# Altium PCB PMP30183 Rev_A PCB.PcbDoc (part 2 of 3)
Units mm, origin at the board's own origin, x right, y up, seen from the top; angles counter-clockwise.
Board outline 88.14 x 173.35 mm, 4 copper layers (Top Layer, Signal Layer 1, Signal Layer 2, Bottom Layer), stack 2.028 mm thick; 250 components, 133 nets, 589 pads, 226 vias.
Unrouted connection lines stored in the file: 1.
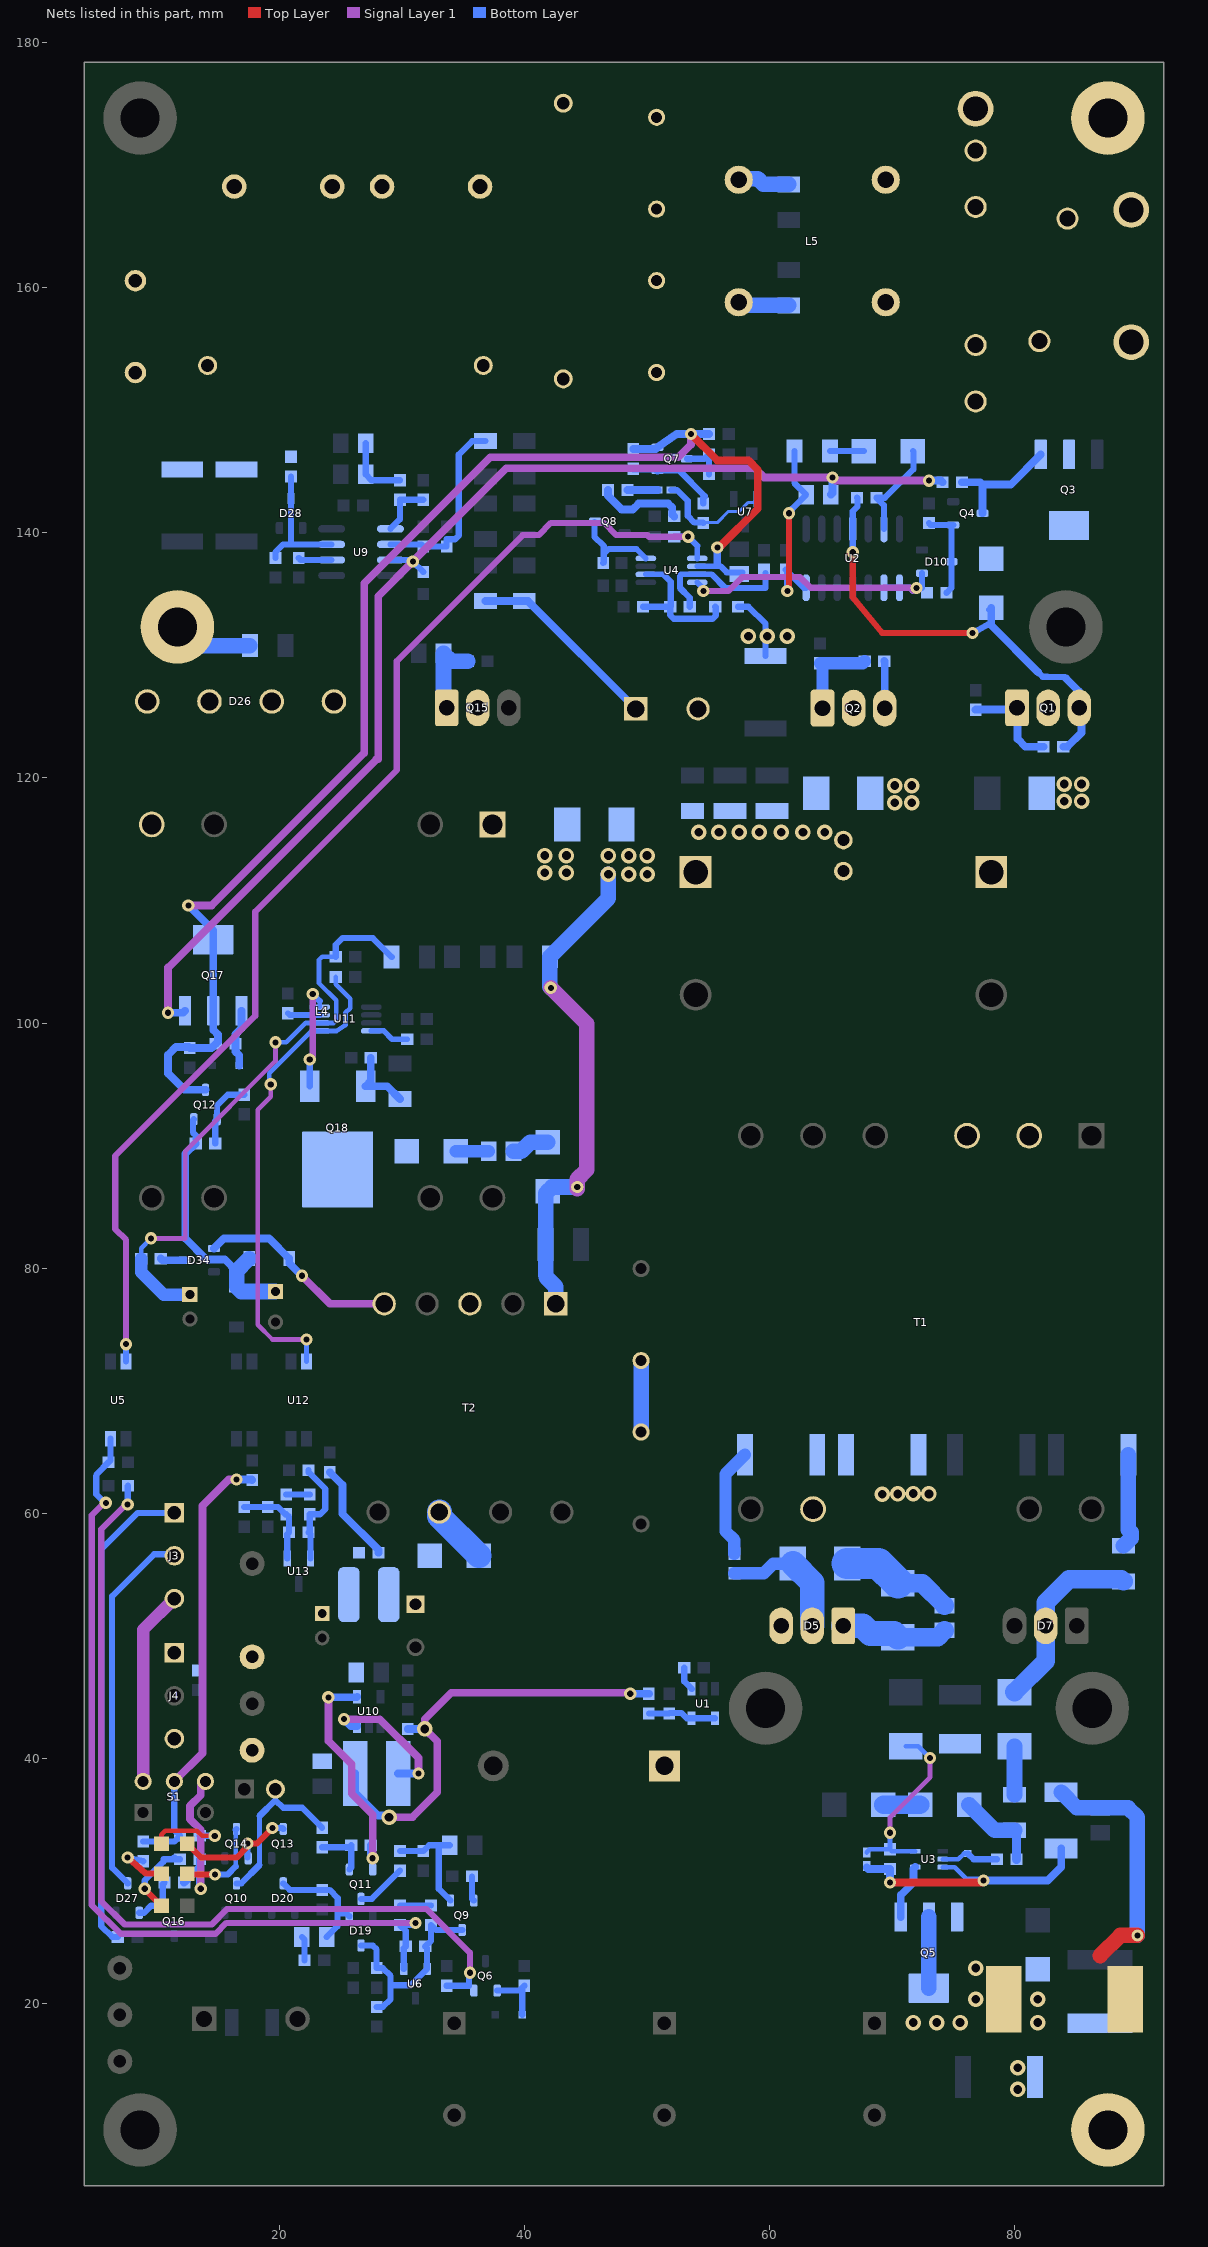
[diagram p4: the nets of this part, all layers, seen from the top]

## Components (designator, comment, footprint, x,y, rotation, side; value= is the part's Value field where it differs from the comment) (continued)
R86 "CRCW060310K0FKEA" 0603#1 19.05,59.69 r90 bottom
RT1 "B57237S0479M000" S237 8.255,156.845 r90 top
RV1 "B72220S0271K101" Epcos_B72220S0271K101 83.185,160.655 r270 top
S1 "200USP1T1A1M2RE" SW_200USP1T1A1M2 11.43,36.83 r90 top
T1 "750315800" Wurth_750315800 72.39,75.565 r270 top
T2 "7508110338" Wurth_7508110338 35.56,68.58 r270 top
TP1 "TESTPOINT" PAD_115mil-80milhole#1 89.535,166.37 r0 top
TP2 "TESTPOINT" PAD_115mil-80milhole#2 86.36,44.069 r0 top
TP3 "5000" Keystone5000 6.985,15.24 r180 top
TP4 "5001" Keystone5001 6.985,22.86 r180 top
TP5 "TESTPOINT" PAD_115mil-80milhole#2 87.63,173.863 r0 top locked
TP6 "TESTPOINT" PAD_115mil-80milhole#2 8.636,9.652 r0 top locked
TP7 "TESTPOINT" PAD_115mil-80milhole#2 8.636,173.863 r0 top locked
TP8 "TESTPOINT" PAD_115mil-80milhole#2 87.63,9.652 r0 top locked
TP9 "5003" Keystone5003 6.985,19.05 r180 top
TP10 "TESTPOINT" PAD_115mil-80milhole#2 59.69,44.069 r90 top
TP11 "TESTPOINT" PAD_115mil-80milhole#2 84.201,132.334 r0 top
TP12 "TESTPOINT" PAD_115mil-80milhole#2 11.684,132.334 r90 top
TP17 "TESTPOINT" PAD_115mil-80milhole#1 76.835,174.625 r90 top
TP19 "TESTPOINT" PAD_115mil-80milhole#1 89.535,155.575 r90 top
TP23 "5000" Keystone5000 17.78,48.26 r180 top
TP24 "5001" Keystone5001 17.78,44.45 r180 top
TP26 "5000" Keystone5000 17.78,40.64 r180 top
TP28 "5003" Keystone5003 17.78,55.88 r0 top
U1 "DS90LT012AHMF/NOPB" MF05A_N 54.61,44.45 r270 bottom
U2 "UCC27714DR" D0014A_N 66.81,137.929 r90 bottom
U3 "SN74LVC1G17DCKR" DCK0005A_N 73.025,31.75 r180 bottom
U4 "LM5021MMX-2" MUA08A_N 52.017,136.942 r180 bottom
U5 "TCMT1107" SOP-4 6.858,69.215 r90 bottom
U6 "TL431AIDBZR" DBZ0003A_N 31.115,21.59 r270 bottom
U7 "LMV431AIMF" MF03A_N 58.039,141.732 r270 bottom
U8 "TCMT1107" SOP-4 17.145,69.215 r90 bottom
U9 "UCC28180D" D0008A_N 26.67,138.43 r0 bottom
U10 "TPS560200DBVR" DBV0005A_N 27.305,43.815 r90 bottom
U11 "LM5021MMX-2" MUA08A_N 25.4,100.33 r0 bottom
U12 "TCMT1107" SOP-4 21.59,69.215 r90 bottom
U13 "LMV431BIMFX" MF03A_N 21.59,55.245 r270 bottom
XF1 "01000056Z" Littelfuse_0100-0020_54_56 76.835,168.91 r270 top
XF2 "01000056Z" Littelfuse_0100-0020_54_56 76.835,153.035 r270 top

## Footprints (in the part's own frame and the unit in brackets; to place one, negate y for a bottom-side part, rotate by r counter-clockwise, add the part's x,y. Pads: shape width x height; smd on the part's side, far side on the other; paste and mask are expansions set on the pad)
3M_923345-01-C [mil] "Wire Jumper"
  round 60 hole 38: 1(-50,0) 2(50,0)
  silkscreen extent -94,-44 94,44, body extent -63,-13 63,13, height 74
0603#1 [mm] "0603 from SM-752 data"
  rect 1x0.95 smd: 1(-0.8,0) 2(0.8,0)
  silkscreen extent -1.52,-0.69 1.52,0.69, body extent -0.87,-0.47 0.87,0.47, height 1
0603#2 [mm] "0603 from SM-752 data"
  rect 1x0.95 smd: 1(-0.927,0) 2(0.927,0)
  silkscreen extent -1.52,-0.69 1.52,0.69, body extent -0.87,-0.47 0.87,0.47, height 0.85
0603#3 [mm] "0603 from SM-752 data"
  rect 1x0.95 smd: 1(-0.927,0) 2(0.876,0)
  silkscreen extent -1.52,-0.69 1.52,0.69, body extent -0.87,-0.47 0.87,0.47, height 0.85
0805_HV [mil] "0805 with 30mil clearance between pads"
  rect 50x63 smd: 1(-40,0) 2(40,0)
  silkscreen extent -74,-40 74,40, body extent -43,-29 43,29, height 57
1206 [mm] "1206 from SM-752 data"
  rect 1.3x1.85 smd: 1(-1.45,0) 2(1.45,0)
  silkscreen extent -2.4,-1.21 2.4,1.21, body extent -1.7,-0.9 1.7,0.9, height 1.35
1210 [mm] "1210 from SM-752 data"
  rect 1.3x2.7 smd: 1(-1.45,0) 2(1.45,0)
  silkscreen extent -2.32,-1.57 2.32,1.57, body extent -1.7,-1.35 1.7,1.35, height 1.35
1210_280 [mm] "SMD, 2-Leads, Body 3.6x2.8mm, Height 2.8mm"
  rect 1.1x2.2 smd: 1(-1.65,0) 2(1.65,0)
  silkscreen extent -0.84,-1.4 0.84,1.4, body extent -1.8,-1.4 1.8,1.4, height 2.8
1812 [mm]
  rect 1.6x3.4 smd: 1(-2,0) 2(2,0)
  silkscreen extent -0.8,-1.6 0.8,1.6, body extent -2.4,-1.7 2.4,1.7, height 1.35
2010 [mm] "Chip Capacitor, Body 5.08x2.54mm, IPC Medium Density"
  rect 1.6x2.7 smd: 1(-2.3,0) 2(2.3,0)
  silkscreen extent -3.42,-1.65 3.42,1.65, body extent -2.73,-1.45 2.73,1.45, height 1.66
2220_200 [mm] "Chip Capacitor, Body 5.7x5.0mm, IPC Medium Density"
  rect 1.6x5.3 smd: 1(-2.6,0) 2(2.6,0)
  silkscreen extent -3.69,-2.94 3.69,2.94, body extent -2.95,-2.62 2.95,2.62, height 1.35
2512 [mm] "Chip Resistor, Body 6.3x3.2mm, IPC Medium Density"
  rect 1.3x3.4 smd: 1(-2.95,0) 2(2.95,0)
  silkscreen extent -1.9,-1.6 1.9,1.6, body extent -3.22,-1.67 3.22,1.67, height 0.71
750315814 [mm] "TH, 2-Leads, Dia 1160mil"
  rect 2.54x2.54 hole 1.5: 1(0,6.985)
  round 2.54 hole 1.5: 2(0,-6.985)
  silkscreen extent -14.73,-8.13 14.73,8.76, body extent -14.74,-8.13 14.74,8.13, height 31.48
750316373 [mm] "TH, 8-Leads, Body 35x35mm"
  rect 2.1x2.1 hole 1.6: 1(-15.24,13.905)
  round 2.1 hole 1.6: 2(-15.24,8.825) 5(-15.24,-8.825) 6(-15.24,-13.905) 7(15.24,-13.905) 8(15.24,-8.825) 11(15.24,8.825) 12(15.24,13.905)
  silkscreen extent -18.3,-17.5 17.5,17.5, body extent -17.5,-17.5 17.5,17.5, height 32
CAPPR3p5-8x16 [mm] "Kemet G8 package from ESY series 10/9/2012"
  rect 1.45x1.45 hole 0.95: 1(-1.75,0)
  round 1.45 hole 0.95: 2(1.75,0)
  silkscreen extent -5.91,-4.25 4.25,4.25, body extent -4.22,-4.24 4.24,4.24, height 18.01
CAPPR750W80D1600H3000 [mm] "Capacitor, Electrolytic, Radial; Body 16 x 30 mm (Dia.xH typ); Pin Spacing 7.5 mm (typ)"
  rect 1.85x1.85 hole 1.1: 1(-3.75,0)
  round 1.85 hole 1.1: 2(3.75,0)
  silkscreen extent -8.3,-8.3 8.3,8.3, body extent -8.19,-8.24 8.23,8.24, height 32.01
CAPRR2250W80L2550T850H1750 [mm] "PANASONIC"
  round 1.55 hole 1.05: 1(-11.25,0) 2(11.25,0)
  silkscreen extent -12.75,-4.25 12.75,4.25, body extent -12.75,-4.25 12.75,4.25, height 17.5
D0008A_N [mm] "SOIC, 8-Leads, Body 4.9x3.9mm, Pitch 1.27mm, IPC Medium Density"
  oval 2.2x0.6 smd: 1(-2.4,1.905) 2(-2.4,0.635) 3(-2.4,-0.635) 4(-2.4,-1.905) 5(2.4,-1.905) 6(2.4,-0.635) 7(2.4,0.635) 8(2.4,1.905)
  silkscreen extent -3.3,-2.5 0.9,2.5, body extent -3,-2.45 3,2.45, height 1.63
D0014A_N [mm] "SOIC, 14-Leads, Body 8.7x3.9mm, Pitch 1.27mm, IPC Medium Density"
  oval 2.2x0.6 smd: 1(-2.4,3.81) 2(-2.4,2.54) 3(-2.4,1.27) 4(-2.4,0) 5(-2.4,-1.27) 6(-2.4,-2.54) 7(-2.4,-3.81) 8(2.4,-3.81) 9(2.4,-2.54) 10(2.4,-1.27) 11(2.4,0) 12(2.4,1.27) 13(2.4,2.54) 14(2.4,3.81)
  silkscreen extent -3.3,-4.4 0.9,4.4, body extent -3.02,-4.32 3.02,4.32, height 1.59
DBV0005A_N [mm] "SOT23, 5-Leads, Body 2.9x1.6mm, Pitch 0.95mm, Lead Span 2.8mm, IPC Medium Density"
  rect 1.1x0.65 smd: 1(-1.2,0.95) 2(-1.2,0) 3(-1.2,-0.95) 4(1.2,-0.95) 5(1.2,0.95)
  silkscreen extent -0.25,-1.55 0.25,1.55, body extent -1.42,-1.46 1.42,1.46, height 1.08
DBZ0003A_N [mm] "SOT23, 3-Leads, Body 2.9x1.3mm, Pitch 0.95mm, Lead Span 2.4mm, IPC Medium Density"
  rrect17% 1x0.6 smd: 1(-1.2,0.95) 2(-1.2,-0.95) 3(1.2,0)
  silkscreen extent -1.65,-1.5 0.7,1.5, body extent -1.26,-1.46 1.26,1.46, height 0.98
DCK0005A_N [mm] "SOT353, 5-Leads, Body 2x1.3mm, Pitch 0.65mm, Lead Span 2.1mm, IPC Medium Density"
  rrect25% 0.85x0.4 smd: 1(-1.125,0.65) 2(-1.125,0) 3(-1.125,-0.65) 4(1.125,-0.65) 5(1.125,0.65)
  silkscreen extent -1.48,-1.02 0.55,1.1, body extent -1.14,-1 1.14,1, height 0.95
DPAK [mm] "D-PAK, 3-Pads, Body 6.22x6.73mm (max), TO-252AA using nominal STEP model"
  rrect6% 2.6x1.6 smd: 1(-3.4,2.28) 3(-3.4,-2.28)
  rrect2% 6.2x5.8 smd paste-2.9: 4(3.4,0)
  silkscreen extent -4.5,-3.3 4.7,3.28, body extent -3.86,-3.29 5.84,3.29, height 2.48
Epcos_B72220S0271K101 [mm] "TH, 2-Leads, Dia 21.5mm, Pin Spacing 10mm"
  round 1.8 hole 1.3: 1(-5,1.15) 2(5,-1.15)
  silkscreen extent -10.75,-2.7 10.75,2.7, body extent -10.66,-2.7 10.75,2.7, height 25.48
GBU [mm] "Comchip / Diodes Inc diode bridge"
  round 2 hole 1.5: 1(-7.62,0) 2(-2.54,0) 3(2.54,0) 4(7.62,0)
  silkscreen extent -11.15,-1.78 11.15,1.78, body extent -11.15,-1.76 11.15,1.8, height 21.55
IND_WE-CMB_L [mm] "Wurth"
  round 2.3 hole 1.321: 2(-5,6) 4(5,6) 7(5,-6) 9(-5,-6)
  silkscreen extent -13.75,-9.25 13.75,9.25, body extent -13.75,-9.25 13.75,9.25, height 33.02
Keystone5000 [mil] "For Keystone 500x miniature loop terminals"
  round 80 hole 40: 1(0,0)
  silkscreen extent -58,-58 58,58, body extent -49,-49 49,49, height 182
Keystone5001 [mil] "For Keystone 500x miniature loop terminals"
  round 80 hole 40: 1(0,0)
  silkscreen extent -58,-58 58,58, body extent -49,-49 49,49, height 182
Keystone5003 [mil] "For Keystone 500x miniature loop terminals"
  round 80 hole 40: 1(0,0)
  silkscreen extent -58,-58 58,58, body extent -49,-49 49,49, height 182
LED_LTST-C170 [mm] "LITE-ON"
  rect 1.2x1.2 smd: 1(-1.05,0) 2(1.05,0)
  silkscreen extent -1.6,-1 2.2,1, body extent -1.05,-0.67 1.05,0.67, height 1.1
Littelfuse_0100-0020_54_56 [mm] "Littelfuse"
  round 1.8 hole 1.3: 1(-2.3,0) 2(2.3,0)
  silkscreen extent -2.25,-2.97 2.25,2.97, body extent -2.55,-2.97 2.55,2.97, height 10.6
LTST-C170KGKT_Green [mm] "LITE-ON"
  rect 1.2x1.2 smd: 1(-1.05,0) 2(1.05,0)
  silkscreen extent -1.6,-1 2.2,1, body extent -1.05,-0.67 1.05,0.67, height 1.1
MF03A_N [mm] "SOT23, 3-Leads, Body 2.9x1.3mm, Pitch 0.95mm, Lead Span 2.4mm, IPC Medium Density"
  rect 1.3x0.6 smd: 1(-1.05,0.95) 2(-1.05,-0.95) 3(1.05,0)
  silkscreen extent -1.17,-1.5 0.7,1.92, body extent -0.7,-1.5 0.7,1.5, height 1.12
MF05A_N [mm] "SOT23, 5-Leads, Body 2.9x1.6mm, Pitch 0.95mm, Lead Span 2.8mm, IPC Medium Density"
  rect 1.1x0.65 smd: 1(-1.2,0.95) 2(-1.2,0) 3(-1.2,-0.95) 4(1.2,-0.95) 5(1.2,0.95)
  silkscreen extent -1.32,-1.55 0.25,1.95, body extent -0.9,-1.55 0.9,1.55, height 1.19
ML_500x500 [mm] "Rubycon"
  rect 1.2x1.2 hole 0.711: 1(-1,0)
  round 1.2 hole 0.711: 2(1,0)
  silkscreen extent -2.75,-2.75 2.75,2.75, body extent -2.73,-2.75 2.75,2.75, height 6.51
Molex_39357-0003 [mm] "Terminal Block, 3.5 mm, 3x1, TH"
  rect 1.6x1.6 hole 1.1: 1(-3.5,0)
  round 1.6 hole 1.1: 2(0,0) 3(3.5,0)
  silkscreen extent -5.61,-3.45 5.25,3.84, body extent -5.25,-3.45 5.16,3.84, height 8.51
Molex_0022284023 [mm] "Header, 2.54mm, 2x1, TH"
  rect 1.55x1.55 hole 1.02: 1(-1.27,0)
  round 1.55 hole 1.02: 2(1.27,0)
  silkscreen extent -2.54,-1.24 2.54,1.5, body extent -2.54,-1.24 2.54,1.24, height 8.4
MUA08A_N [mm] "TSOP, 8-Leads, Body 3x3mm, Pitch 0.65mm, IPC Medium Density"
  oval 1.7x0.45 smd: 1(-2.1,0.975) 2(-2.1,0.325) 3(-2.1,-0.325) 4(-2.1,-0.975) 5(2.1,-0.975) 6(2.1,-0.325) 7(2.1,0.325) 8(2.1,0.975)
  silkscreen extent -2.22,-1.55 0.85,1.87, body extent -1.6,-1.6 1.6,1.6, height 1.09
PAD_115mil-80milhole#1 [mil]
  round 115 hole 80: 1(0,0)
PAD_115mil-80milhole#2 [mil]
  round 236 hole 126: 1(0,0)
Phoenix_1732720 [mm] "Phoenix Contact"
  rect 2x2 hole 1.3 paste+0 mask+0.05: 1(-3.81,-1.1)
  round 2 hole 1.3 paste+0 mask+0.05: 2(3.81,-1.1)
  silkscreen extent -8.91,-6.4 7.62,6.4, body extent -8.19,-6.4 7.62,6.4, height 18.3
S237 [mm] "EPCOS"
  round 1.75 hole 1.1: 1(-3.75,0) 2(3.75,0)
  silkscreen extent -7.5,-3.5 7.5,3.5, body extent -7.47,-3.5 7.47,3.5, height 21.99
SMA [mm] "Molded Diode, 2-Leads, Body 4.3x2.6mm, IPC Medium Density, based on OnSemi component dimensions and land pattern"
  rect 2x2 smd: 1(-2,0) 2(2,0)
  silkscreen extent -3.66,-1.57 2.79,1.57, body extent -2.6,-1.3 2.6,1.3, height 2.42
SMB [mm] "Molded Diode, 2-Leads, Body 5.4x3.6mm, IPC Medium Density, based on OnSemi component dimensions"
  rect 2.159x2.743 smd: 1(-2.21,0) 2(2.21,0)
  silkscreen extent -3.94,-2.08 3.18,2.08, body extent -2.7,-1.8 2.7,1.8, height 2.32
SMQ_2200X2500 [mm] "United Chemi-Con Inc"
  rect 2.6x2.6 hole 2: 1(-5,0)
  round 2.6 hole 2: 2(5,0)
  silkscreen extent -11.6,-11.6 11.6,11.6, body extent -11.41,-11.48 11.47,11.48, height 27.01
SOD-123 [mm] "On Semi recommended land pattern"
  rect 0.915x1.22 smd: 1(-1.637,0) 2(1.637,0)
  silkscreen extent -2.74,-1.17 2.03,1.17, body extent -1.93,-0.9 1.93,0.9, height 1.35
sod-323 [mm] "NXP recommended land pattern"
  rect 0.6x0.6 smd paste-0.05: 1(-1.1,0) 2(1.1,0)
  silkscreen extent -2.06,-0.86 1.53,0.86, body extent -1.3,-0.67 1.3,0.68, height 1.1
SOD-523 [mm] "NXP Semiconductor recommended land pattern, nominal STEP model"
  rect 0.8x0.6 smd paste-0.05: 1(-0.55,0) 2(0.55,0)
  silkscreen extent -1.6,-0.63 1.2,0.64, body extent -0.8,-0.4 0.8,0.4, height 0.72
SOP-4 [mm] "Vishay Half Pitch Mini-Flat Package"
  rect 1.3x0.9 smd: 1(-3.15,0.635) 2(-3.15,-0.635) 3(3.15,-0.635) 4(3.15,0.635)
  silkscreen extent -2.2,-1.41 2.2,1.39, body extent -3.5,-1.4 3.5,1.4, height 2.12
SOT-23 [mm] "SOT23, 3-Leads, Body 2.9x1.3mm, Pitch 0.95mm, Lead Span 2.5mm, IPC Medium Density"
  rrect50% 1x0.6 smd: 1(-1.2,0.95) 2(-1.2,-0.95) 3(1.2,0)
  silkscreen extent -1.62,-1.5 0.7,1.5, body extent -1.16,-1.45 1.21,1.45, height 1
SOT-223 [mm] "SOT223/SC73, 4-Leads, Body 6.5x3.5mm, Pitch 2.3mm, Lead Span 7mm, IPC Medium Density"
  rrect10% 2.4x1 smd: 1(-2.9,2.3) 2(-2.9,0) 3(-2.9,-2.3)
  rrect4% 2.4x3.3 smd: 4(2.9,0)
  silkscreen extent -3.33,-3.35 1.4,3.35, body extent -3.5,-3.25 3.5,3.25, height 1.62
SW_200USP1T1A1M2 [mm] "TH, 5-Leads, Body 7x4.5mm, Pitch 2.54mm"
  rect 1.4x1.4 hole 0.9: 1(-1.27,2.54)
  round 1.4 hole 0.9: 3(-1.27,-2.54) 4(1.27,2.54) 5(1.27,0) 6(1.27,-2.54)
  silkscreen extent -2.7,-3.63 2.38,3.63, body extent -2.37,-3.62 2.38,3.63, height 11.13
TO-220-F2 [mm] "CREE"
  rect 1.9x1.9 hole 1.4: 1(-2.54,0)
  round 1.9 hole 1.4: 2(2.54,0)
  silkscreen extent -5.25,-1.64 5.26,3.01, body extent -5.25,-1.64 5.26,3.01, height 19.09
TO-220AB [mm] "Copied from Altium's version of TO3B"
  rrect25% 1.93x3 hole 1.27: 1(-2.54,0)
  oval 1.93x3 hole 1.27: 2(0,0) 3(2.54,0)
  silkscreen extent -5.61,-1.49 5.61,3.2, body extent -5.61,-1.49 5.61,3.2, height 19.42
VY2_1250x500x1650 [mm] "TH, 2- Leads, Body 12.5x5mm, Pin Spacing 7.5mm"
  round 1.4 hole 0.9: 1(-3.75,0) 2(3.75,0)
  silkscreen extent -6.25,-2.5 6.25,2.5, body extent -6.2,-2.5 6.25,2.5, height 16.49
WE-FI_1900x1050 [mm] "TH, 2-Leads, Dia 19mm, Pin Spacing 8mm"
  round 2 hole 1.25: 1(0,4) 2(0,-4)
  silkscreen extent -9.5,-5.25 9.5,5.25, body extent -9.5,-5.25 9.5,5.25, height 19
WE-PD2-S [mm] "WURTH"
  rrect50% 1.75x4.5 smd: 1(-1.625,0) 2(1.625,0)
  Top Layer region: 1.375,-2.25 0.75,-2.25 0.75,2.25 1.375,2.25
  Top Layer region: -1.375,2.25 -0.75,2.25 -0.75,-2.25 -1.375,-2.25
  silkscreen extent -0.4,-2.1 0.4,2.12, body extent -2.25,-2 2.25,2, height 3.18
WE-PD_1280 [mm] "Wurth Elektronik recommended land pattern"
  rect 2.9x5.4 smd: 1(-4.95,0) 2(4.95,0)
  silkscreen extent -6,-6 6,6, body extent -6,-6 6,6, height 8.01
WE-SPC_4838 [mm] "WURTH"
  rect 2x5.3 smd: 1(-1.75,0) 2(1.75,0)
  silkscreen extent -0.48,-2.65 0.48,2.65, body extent -2.55,-2.55 2.55,2.55, height 4.1
Wurth_750315800 [mm] "TH, 10-Leads, Body 37.34x35.56mm, Pitch 5.08mm"
  rect 2.1x2.1 hole 1.6: 1(-15.24,13.905)
  round 2.1 hole 1.6: 2(-15.24,8.825) 3(-15.24,3.745) 4(-15.24,-3.745) 5(-15.24,-8.825) 6(-15.24,-13.905) 7(15.24,-13.905) 8(15.24,-8.825) 11(15.24,8.825) 12(15.24,13.905)
  silkscreen extent -18.67,-17.78 18.67,17.78, body extent -18.67,-17.78 18.67,17.78, height 34.29
Wurth_7508110338 [mm] "TH, 9-Leads, Body 24.38x20.32mm"
  rect 1.9x1.9 hole 1.4: 1(-8.5,7)
  round 1.9 hole 1.4: 2(-8.5,3.5) 3(-8.5,0) 4(-8.5,-3.5) 5(-8.5,-7) 6(8.5,-7.5) 7(8.5,-2.5) 8(8.5,2.5) 9(8.5,7.5)
  silkscreen extent -12.19,-10.16 12.19,10.16, body extent -12.19,-10.16 12.19,10.16, height 16
ZL_630x1100 [mm] "RUBYCON"
  rect 1.25x1.25 hole 0.75: 1(-1.25,0)
  round 1.25 hole 0.75: 2(1.25,0)
  silkscreen extent -3.45,-3.45 3.45,3.45, body extent -3.37,-3.39 3.4,3.39, height 12.51
ZLJ_500x1100 [mm] "TH, 2-Leads, Dia 5mm,  Lead Spacing 2mm"
  rect 1.25x1.25 hole 0.75: 1(-1,0)
  round 1.25 hole 0.75: 2(1,0)
  silkscreen extent -2.75,-2.75 2.75,2.75, body extent -2.73,-2.75 2.75,2.75, height 12.51

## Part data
C1: "CAP, CERM, 0.01 µF, 630 V, +/- 10%, X7R, 1206"
C2 C3 C46: library part GRM32DR72J473KW01L, "CAP, CERM, 0.1 µF, 630 V, +/- 10%, X7T 1210"
C4: "CAP, CERM, 1000 pF, 630 V, +/- 5%, X7R, 0805"
C5 C8 C26 C45 C54: "CAP, CERM, 0.1uF, 50V, +/-10%, X7R, 0603"
C6: "CAP, CERM, 330 pF, 250 V, +/- 10%, X7R, 0603"
C7 C19 C20 C25 C32: "CAP, CERM, 1uF, 25V, +/-10%, X7R, 0603"
C9: "CAP, CERM, 220 pF, 630 V, +/- 5%, C0G/NP0, 1206"
C10 C11 C12: library part 400KXW100MEFC16X30, "CAP, AL, 1000 µF, 50 V, +/- 20%, TH"
C13: "CAP, CERM, 10 µF, 50 V, +/- 20%, X7R, 1210"
C14: "CAP, CERM, 1 µF, 250 V, +/- 10%, X7R, 2220"
C15 C16 C34 C60: "CAP, CERM, 4700 pF, 440 V, +/- 20%, Y5U, TH, 12.5x5mm"
C17: "CAP, CERM, 0.1 µF, 250 V, +/- 10%, X7R, 1812"
C18 C22 C24: "CAP, CERM, 100 pF, 50 V, +/- 5%, C0G/NP0, 0603"
C21 C28: "CAP, CERM, 1 µF, 50 V, +/- 10%, X7R, 0805"
C23 C55: "CAP, CERM, 0.33 µF, 16 V, +/- 10%, X7R, 0603"
C27 C39 C57: "CAP, CERM, 1000 pF, 50 V, +/- 10%, X7R, 0603"
C29: "CAP, CERM, 1000 pF, 50 V, +/- 10%, X8R, 0603"
C30: "CAP, CERM, 0.33 µF, 50 V, +/- 10%, X7R, 0805"
C31: "CAP, CERM, 4.7 µF, 25 V, +/- 10%, X7R, 0805"
C33: "CAP, CERM, 1000 pF, 630 V, +/- 10%, X7R, 1206"
C35 C36: library part ESMQ451VSN101MP25S, "CAP, AL, 150 µF, 450 V, +/- 20%, TH"
C37: "CAP, Film, 0.47 µF, 275 V, +/- 20%, TH"
C38: library part ECQ-U2A474ML, "CAP, Film, 1 µF, 275 V, +/- 20%, TH"
C40 C51: "CAP, CERM, 4.7 µF, 25 V, +/- 10%, X5R, 0805"
C41: "CAP, CERM, 2.2 µF, 16 V, +/- 10%, X7R, 0805"
C42: "CAP, CERM, 0.22 µF, 16 V, +/- 10%, X7R, 0603"
C43: "CAP, CERM, 820pF, 50V, +/-5%, C0G/NP0, 0603"
C44: "CAP, CERM, 2200 pF, 50 V, +/- 10%, X7R, 0603"
C47: library part ESY477M016AG8AA, "CAP, AL, 470uF, 16V, +/-20%, TH"
C48: library part 25ML22MEFC5X5, "CAP, AL, 100 µF, 16 V, +/- 20%, TH"
C49 C56: "CAP, CERM, 1uF, 16V, +/-10%, X7R, 0603"
C50: library part 35ZL56MEFCTA6.3X11, "CAP, AL, 47 µF, 35 V, +/- 20%, 0.25 ohm, TH"
C52: "CAP, CERM, 22 µF, 6.3 V, +/- 20%, X5R, 0805"
C53: library part 35ZLJ47MTA5X11, "CAP, AL, 10 µF, 50 V, +/- 20%, 1.4 ohm, TH"
C58: "CAP, CERM, 56pF, 50V, +/-5%, C0G/NP0, 0603"
C59: "CAP, CERM, 0.047 µF, 50 V, +/- 10%, X8R, 0603"
D1 D6: "Diode, Ultrafast, 600 V, 1 A, AEC-Q101, SMA"
D2 D11: "Diode, TVS, Uni, 150 V, 600 W, SMB"
D3 D9: "Diode, Schottky, 200 V, 3 A, SMB"
D4 D8: "Diode, Ultrafast, 600 V, 2 A, SMB"
D5 D7: library part VS-48CTQ060PBF, "Diode, Schottky, 200 V, 20 A, TH"
D10 D19 D20 D27 D28 D34: "Diode, Switching, 200 V, 0.2 A, SOT-23"
D12: "Diode, Zener, 5.1 V, 300 mW, SOD-523"
D13 D17: "Diode, TVS, Uni, 58 V, 400 W, SMA"
D14: "Diode, Schottky, 30 V, 0.2 A, SOD-323"
D15: "Diode, Ultrafast, 200 V, 1 A, SMA"
D16 D29: "Diode, Zener, 13 V, 200 mW, SOD-323"
D18: "Diode, Zener, 6.8 V, 300 mW, SOD-523"
D21: "LED, Yellow , SMD"
D22 D23: "LED, Green, SMD"
D24: library part MURS140-13-F, "Diode, Standard, 600 V, 3 A, SMB"
D25: library part C3D04060A, "Diode, X-Series PFC, 600 V, 6 A, TH"
D26: library part GBU8005, "Diode, Switching-Bridge, 600 V, 8 A, TH"
D30: library part STPS130A, "Diode, Schottky, 150 V, 1 A, SMA"
D31: "Diode, TVS, Uni, 120 V, 400 W, SMA"
D32: "Diode, Fast Rectifier, 800 V, 1 A, SMA"
D33: library part RF071M2S, "Diode, Ultrafast, 200 V, 1 A, SOD-123"
D35: library part MMSZ4711-V, "Diode, Zener, 27 V, 500 mW, SOD-123"
J1: "Jumper Wire, 100mil spacing, pkg of 200, TH"
J2: "Terminal Block, 2x1, 7.62mm, TH"
J3 J4: "Terminal Block, 3.5 mm, 3x1, Tin, TH"
J5: "Header, 2.54mm, 2x1, Tin, TH"
L1: library part 750315814, "Inductor, Toroid, 52 µH, 0.052 ohm, TH"
L2: "Inductor, Shielded Drum Core, Ferrite, 1 mH, 0.6 A, 1.82 ohm, SMD"
L3 L8: "Inductor, Toroid, Ferrite, 29 µH, 7.8 A, 0.015 ohm, TH"
L4: "Inductor, 500 µH, 0.03 ohm, TH"
L5: library part 744824310, "Coupled inductor, 3.3 mH, 4 A, 0.035 ohm, +/- 30%, TH"
L10: "Inductor, Shielded Drum Core, Ferrite, 4.7 µH, 1.82 A, 0.11 ohm, SMD"
L11: "Inductor, Shielded Drum Core, Ferrite, 22 µH, 1.1 A, 0.185 ohm, SMD"
Q1 Q2: "MOSFET, N-CH, 550 V, 17 A, TO-220AB"
Q3: library part FQT7N10LTF, "MOSFET, N-CH, 600 V, 300 mA, SOT-223"
Q4: "MOSFET, N-CH, 60 V, 0.24 A, SOT-23"
Q5: "MOSFET, P-CH, -240 V, -0.48 A, SOT-223"
Q6 Q8: library part "MMBT3904, Fairchild Semiconductor", "Transistor, NPN, 40 V, 0.2 A, SOT-23"
Q7 Q11: library part "MMBT3906, Fairchild Semiconductor", "Transistor, PNP, 40V, 0.2A, SOT-23"
Q9 Q10 Q13 Q14 Q16: "MOSFET, N-CH, 50 V, 0.22 A, SOT-23"
Q12: library part "MMBT2907A, Fairchild Semiconductor", "Transistor, PNP, 60 V, 0.8 A, SOT-23"
Q15: library part IPP50R199CP, "MOSFET, N-CH, 550 V, 23 A, TO-220AB"
Q17: library part "PZT2222A, Fairchild Semiconductor", "Transistor, NPN, 40 V, 0.5 A, SOT-223"
Q18: library part SPD04N80C3, "MOSFET, N-CH, 800 V, 2 A, DPAK"
R1: "RES, 2.21, 1%, 0.125 W, 0805"
R2: "RES, 2.20 ohm, 1%, 0.25W, 1206"
R3 R45 R46 R54: "RES, 100, 1%, 0.1 W, 0603"
R4: "RES, 29.4 k, 1%, 0.1 W, 0603"
R5 R6 R9 R12: "RES, 68.1, 1%, 1 W, 2512"
R7 R10: "RES, 4.75, 1%, 0.1 W, 0603"
R8 R13 R36 R41 R43 R51 R58 R67 R70 R86: "RES, 10.0k ohm, 1%, 0.1W, 0603"
R11 R17 R18 R19 R53: "RES, 1.00 k, 1%, 0.1 W, 0603"
R14: library part CSR2512FG68L0, "RES, 0.068, 1%, 2 W, 2512"
R15: "RES, 4.75 k, 1%, 0.1 W, 0603"
R16: "RES, 4.75 k, 1%, 0.25 W, 1206"
R20: "RES, 698k ohm, 1%, 0.25W, 1206"
R21: "RES, 23.7 k, 1%, 0.1 W, 0603"
R22: "RES, 3.32 k, 1%, 0.1 W, 0603"
R23 R84: "RES, 2.21k ohm, 1%, 0.1W, 0603"
R24: "RES, 68.1 k, 1%, 0.75 W, 2010"
R25 R29: "RES, 715k ohm, 1%, 0.25W, 1206"
R26: "RES, 16.5 k, 1%, 0.1 W, 0603"
R27 R33 R34: "RES, 68.1 k, 1%, 0.1 W, 0603"
R28: "RES, 33.2, 1%, 1 W, 2512"
R30: "RES, 1.21 M, 1%, 0.1 W, 0603"
R31 R39 R44: "RES, 47.5 k, 1%, 0.1 W, 0603"
R32 R77: "RES, 49.9 ohm, 1%, 0.1W, 0603"
R35: "RES, 221 k, 1%, 0.1 W, 0603"
R37: "RES, 15.0 k, 1%, 0.1 W, 0603"
R38: "RES, 6.81k ohm, 1%, 0.1W, 0603"
R40 R42 R47 R50 R85: "RES, 100 k, 1%, 0.1 W, 0603"
R48: "RES, 16.2 k, 1%, 0.1 W, 0603"
R49: "RES, 475 k, 1%, 0.1 W, 0603"
R52 R65: "RES, 33.2 k, 1%, 0.1 W, 0603"
R55 R60: "RES, 475 k, 1%, 0.25 W, 1206"
R56 R59 R62: "RES, 1.00 M, 1%, 0.25 W, 1206"
R57: "RES, 2.21 ohm, 1%, 0.125W, 0805"
R61 R63: "RES, 0.075, 1%, 2 W, 2512"
R64: "RES, 221 ohm, 1%, 0.1W, 0603"
R66: "RES, 38.3 k, 1%, 0.1 W, 0603"
R68: library part CRCW06031R00FKEA, "RES, 0 Ohm, 1%, 0.1 W, 0603"
R69: "RES, 17.8 k, 1%, 0.1 W, 0603"
R71 R73 R75: "RES, 332k ohm, 1%, 0.25W, 1206"
R72: "RES, 51 ohm, 5%, 0.125W, 0805"
R74: "RES, 10.0, 1%, 0.1 W, 0603"
R76: "RES, 22.1, 1%, 0.1 W, 0603"
R78: "RES, 61.9 k, 1%, 0.1 W, 0603"
R79: "RES, 392, 1%, 0.1 W, 0603"
R80: "RES, 20.0 k, 1%, 0.1 W, 0603"
R81: "RES, 1.82, 1%, 0.25 W, 1206"
R82: "RES, 27.4 k, 1%, 0.1 W, 0603"
R83: "RES, 86.6 k, 1%, 0.1 W, 0603"
RT1: "Thermistor NTC, 4.70 ohm, 20%, 15x7mm"
RV1: "Varistor 275 VAC, 100 A, TH"
S1: "Switch, SPDT, On-On, 2 Pos, TH"
T1: "Transformer, 2 mH, TH"
T2: "Transformer, 1.5 mH, TH"
TP1 TP2 TP5 TP6 TP7 TP8 TP10 TP11 TP12 TP17 TP19: library part PAD_115mil-80milhole, "115mil pad, 80mil hole"
TP3 TP23 TP26: "Test Point, Miniature, Red, TH"
TP4 TP24: "Test Point, Miniature, Black, TH"
TP9 TP28: "Test Point, Miniature, Orange, TH"
U1: "Resistor-Programmable Temperature Switch, 5 pin SOT-23"
U2: "High-Speed,4A, 600V High-side Low-side Gate Driver Device, D0014A"
U3: "SINGLE SCHMITT-TRIGGER BUFFER, DCK0005A"
U4 U11: "AC-DC Current Mode PWM Controller, 8-pin MSOP"
U5 U8 U12: "Optocoupler, 3.75 kV, 80-160% CTR, SMD-4"
U6: "Adjustable Precision Shunt Regulator, 34 ppm / degC, 100 mA, -40 to 85 degC, 3-pin SOT-23 (DBZ), Green (RoHS & no Sb/Br)"
U7: "Low-Voltage (1.24V) Adjustable Precision Shunt Regulator, 3-pin SOT-23"
U9: "8-PIN CONTINUOUS CONDUCTION MODE (CCM) PFC CONTROLLER, D0008A"
U10: library part TPS560200DBV, "4.5V to 18V Input, 500mA Synchronous Step Down SWIFT Converter with Advanced Eco-mode, DBV0005A"
U13: "Low-Voltage (1.24V) Adjustable Precision Shunt Regulators, 3-pin SOT-23"
XF1 XF2: "Fuse Holder, 10A, TH"

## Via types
v1: diameter 1, hole 0.5, Top Layer to Bottom Layer, 163 vias
v2: diameter 1.27, hole 0.711, Top Layer to Bottom Layer, 63 vias

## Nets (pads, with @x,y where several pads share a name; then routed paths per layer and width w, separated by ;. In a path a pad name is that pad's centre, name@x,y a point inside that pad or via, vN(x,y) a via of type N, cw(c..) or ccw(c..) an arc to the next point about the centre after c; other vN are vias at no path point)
+3.3VSEC: C52.1 J4.3 L11.2 R3.2 R54.1 R67.2 R78.2 S1.6 TP26.1 | length 50.9
  Signal Layer 1 w0.635: v1(13.589,29.337) 13.589,34.143 12.698,35.033 12.698,36.087 13.589,36.977 13.589,37.719 S1.6@13.97,38.1 ; v2(28.956,35.179) 30.861,35.179 32.893,37.211 32.893,41.364 v2(31.877,42.38) 31.877,43.18 34.036,45.339 48.552,45.339 v1(48.641,45.25)
  Bottom Layer w0.635: R67.2@12.23,29.845 13.5,31.115 ; R54.1@13.5,31.75 13.5,31.115 ; v1(13.589,29.337) 13.462,29.337 13.5,29.375 13.5,31.115 ; L11.2@26.19,38.735 26.19,37.183 28.067,35.306 28.829,35.306 v2(28.956,35.179) ; R78.2@30.48,42.38 v2(31.877,42.38) ; v1(48.641,45.25) R3.2@50.165,45.25
+3.3VSW: R45.1 R46.1 R53.2 S1.5 | length 36.2
  Signal Layer 1 w0.635: S1.5@11.43,38.1 13.73,40.4 13.73,60.593 15.875,62.738 v1(16.51,62.738)
  Bottom Layer w0.508: R46.1@8.89,33.185 11.43,33.185 R45.1@11.9,33.655 11.43,34.125 S1.5@11.43,38.1
  Bottom Layer w0.635: v1(16.51,62.738) 17.742,62.738 R53.2@17.78,62.7
"+12V SWITCHED": C45.1 Q17.3 R1.1 R11.2 U9.7 | length 98
  Signal Layer 1 w0.635: v1(10.922,100.838) 10.922,104.521 27.94,121.539 28.067,121.539 28.067,134.836 v1(30.899,137.668) 38.519,145.288 58.801,145.288 59.563,144.526 v1(65.151,144.526) 65.405,144.272 v1(73.025,144.272)
  Bottom Layer w0.508: U9.7@29.07,137.795 30.772,137.795 v1(30.899,137.668) C45.1@31.75,136.817
  Bottom Layer w0.635: v1(10.922,100.838) 12.143,100.838 Q17.3@12.305,101 ; R1.1@65.024,143.129 65.151,143.256 v1(65.151,144.526) ; v1(73.025,144.272) 74.003,144.272 R11.2@74.13,144.145
+12VSEC: C47.1 C51.1 D30.1 L10.1 Q11.2 R41.1 R74.1 R77.2 U10.4 | length 26.5
  Signal Layer 1 w0.635: v1@24.003,45.085 v1(24.003,44.958) 24.003,41.402 25.908,39.497 25.908,37.084 27.62,35.372 v1(27.62,31.823)
  Bottom Layer w0.635: v1(24.003,44.958) 26.298,44.958 U10.4@26.355,45.015 ; R77.2@24.13,63.335 25.146,62.319 25.146,59.944 28.105,56.985 R74.1@28.105,56.769 ; R41.1@27.47,32.885 27.47,31.972 v1(27.62,31.823)
"+24V SWITCHED": C21.1 C32.1 Q7.2 Q12.3 Q17.2 Q17.4 R22.2 R51.1 R70.1 U4.2 | length 113.1
  Top Layer w0.635: v1(53.594,148.082) 55.753,145.923 58.293,145.923 59.055,145.161 59.055,141.986 v1@56.007,138.938
  Signal Layer 1 w0.635: v1(12.573,109.601) 14.478,109.601 26.924,122.047 26.924,135.884 37.217,146.177 52.57,146.177 53.594,147.201 v1(53.594,148.082)
  Bottom Layer w0.457: U4.2@54.117,137.267 56.027,137.267
  Bottom Layer w0.508: 56.027,137.267 56.515,136.779 C21.1@57.785,136.779
  Bottom Layer w0.635: v1(12.573,109.601) 14.605,107.569 Q17.4@14.605,106.8 Q17.2@14.605,101 14.605,99.441 14.986,99.06 14.986,98.477 R70.1@14.821,98.312 14.464,97.955 R51.1@12.7,97.955 12.611,98.044 11.557,98.044 10.922,97.409 10.922,95.885 12.262,94.545 Q12.3@13.97,94.545 ; R22.2@48.895,146.85 50.72,146.85 Q7.2@50.87,147 52.46,148.082 v1(53.594,148.082) C32.1@55.08,148.082 ; 55.753,137.414 v1@55.753,138.469
  other v1: 55.753,138.811
+24VPRIM: C50.1 D33.1 D35.1 Q12.2 R50.2 | length 21.6
  Bottom Layer w0.508: Q12.2@13.02,92.145 12.954,92.079 12.954,91.059 13.17,90.843 R50.2@13.17,90.17
  Bottom Layer w0.635: R50.2@13.17,90.17 12.319,89.319 12.319,82.418 14.013,80.724 14.276,80.724 14.294,80.706 15.546,80.706 16.51,79.742
  Bottom Layer w1.27: D33.1@17.54,80.772 16.51,79.742 D35.1@16.51,78.472 16.897,78.085 C50.1@19.685,78.085
+400V: C35.1 C36.1 C46.1 D24.1 D25.1 D31.2 J1.1 R20.2 R56.2 R71.2 T2.1 | length 57.3
  Signal Layer 1 w1.27: v1(42.164,102.87) 45.085,99.949 45.085,88.011 44.323,87.249 v1(44.323,86.614) v1@44.323,86.487
  Bottom Layer w0.635: R56.2@36.83,134.44 R20.2@40.005,134.44 40.298,134.44 D25.1@49.097,125.641
  Bottom Layer w1.27: v1(42.164,102.87) 42.09,102.944 R71.2@42.09,105.41 46.863,110.183 v2(46.863,112.141) ; T2.1@42.56,77.08 42.56,78.471 41.783,79.248 41.783,79.375 41.73,79.428 C46.1@41.73,81.915 41.73,86.085 D31.2@41.91,86.265 42.259,86.614 v1(44.323,86.614)
  other v2: 48.514,112.141 50.038,112.141 46.863,113.665 48.514,113.665 50.014,113.665
EARTH: C14.1 C34.1 C60.2 TP1.1 TP5.1 TP8.1
NetC1_1: C1.1 C2.1 C3.1 D4.1 J1.2 Q1.2
  other v2: 54.229,115.57 55.88,115.57 57.531,115.57 59.182,115.57 60.96,115.57 62.738,115.57 64.516,115.57
NetC4_1: C4.1 D2.1 D3.1 | length 9.4
  Bottom Layer w1.524: D2.1@70.485,54.28 72.466,54.28 C4.1@74.295,52.451
  Bottom Layer w2.54: D3.1@66.345,55.88 68.885,55.88 D2.1@70.485,54.28
NetC4_2: C4.2 D2.2 D5.1 D5.3 R5.1 T1.8 | length 8.9
  Bottom Layer w1.524: D2.2@70.485,49.86 73.736,49.86 C4.2@74.295,50.419
  Bottom Layer w2.032: D5.1@66.04,50.8 67.6,50.8 68.235,50.165 70.18,50.165 D2.2@70.485,49.86
  other v2: 69.215,61.527 70.485,61.565 73.025,61.565 71.755,61.595
NetC5_1: C5.1 R3.1 U1.4 U1.5 | length 5.6
  Bottom Layer w0.508: R3.1@50.165,43.65 C5.1@51.816,43.65 51.854,43.688 52.81,43.688 53.248,43.25 U1.5@53.66,43.25 U1.4@55.56,43.25
NetC6_1: C6.1 C9.1 D3.2 D5.2 D7.2 D9.2 L1.1 | length 26.4
  Bottom Layer w1.016: C6.1@57.15,55.08 59.525,55.08 60.325,55.88 D3.2@61.925,55.88
  Bottom Layer w1.524: D9.2@80.01,45.39 82.55,47.93 D7.2@82.55,50.8 82.55,52.705 84.455,54.61 88.72,54.61 C9.1@88.9,54.43
  Bottom Layer w2.032: D3.2@61.925,55.88 63.5,54.305 D5.2@63.5,50.8
NetC6_2: C6.2 R6.2 | length 9.1
  Bottom Layer w1.016: C6.2@57.15,56.68 57.15,57.785 56.419,58.516 56.419,63.179 R6.2@58.01,64.77
NetC7_1: C7.1 R1.2 R2.2 U2.7 | length 16.3
  Top Layer w0.508: v1(61.468,135.255) 61.595,135.382 v1(61.595,141.605)
  Bottom Layer w0.508: C7.1@61.341,136.995 C7.1@61.468,136.868 ; v1(61.468,135.255) C7.1@61.468,136.868 ; v1(61.595,141.605) 61.849,141.859 61.849,141.986 R1.2@62.992,143.129 62.05,144.071 R2.2@62.05,146.685 ; U2.7@63,135.529 62.807,135.529 C7.1@61.468,136.868
NetC8_1: C8.1 D6.2 D8.1 Q1.3 R8.2 T1.3 U2.11 | length 37.5
  Top Layer w0.508: v1(66.81,138.429) 66.802,138.42 66.802,134.747 69.215,131.826 v1(76.574,131.826)
  Bottom Layer w0.508: v1(66.81,138.429) U2.11@66.81,140.329 66.81,141.777 67.183,142.15 67.183,142.837 C8.1@67.145,142.875 ; v1(76.574,131.826) 77.939,132.588 ; D6.2@77.946,133.731 D6.2@78.105,133.89 ; 81.915,128.651 82.296,128.27 82.677,128.27 82.704,128.243 84.101,128.243 84.201,128.143
  Bottom Layer w0.635: D6.2@78.105,133.89 78.105,132.461 81.915,128.651 ; R8.2@83.985,122.555 84.328,122.555 85.471,123.698 85.471,125.549 Q1.3@85.293,125.727 85.293,127.051 84.201,128.143
  other v2: 84.074,118.098 85.483,118.098 84.074,119.507 85.483,119.507
NetC8_2: C8.2 D1.1 U2.13 | length 8.3
  Bottom Layer w0.508: U2.13@69.35,140.329 69.35,142.27 C8.2@68.745,142.875 69.431,142.875 71.755,145.199 71.755,146.653 D1.1@71.723,146.685
NetC9_2: C9.2 R9.2 | length 7.8
  Bottom Layer w1.27: C9.2@88.9,57.33 89.535,57.965 89.535,58.42 89.31,58.645 R9.2@89.31,64.77
NetC15_2: C15.2 C16.1 | length 5.8
  Bottom Layer w1.27: C16.1@49.53,66.615 C15.2@49.53,72.45
NetC17_1: C17.1 C19.1 D9.1 D11.1 D12.1 Q5.3 R16.2 U3.5 | length 19.3
  Signal Layer 1 w0.381: v1(69.85,33.909) 69.85,35.179 73.114,38.443 v1(73.114,40.005)
  Bottom Layer w0.381: D12.1@67.945,32.3 68.195,32.55 C19.1@69.85,32.55 ; v1(69.85,33.909) C19.1@69.85,32.55 ; D11.1@71.12,40.97 72.149,40.97 v1(73.114,40.005) ; U3.5@71.9,32.4 70,32.4 C19.1@69.85,32.55
  Bottom Layer w1.27: R16.2@80.01,37.01 D9.1@80.01,40.97
NetC18_1: C18.1 D10.3 Q4.1 R15.1 | length 7.8
  Bottom Layer w0.508: C18.1@73.025,140.805 73.175,140.655 Q4.1@75,140.655 74.86,140.515 D10.3@74.86,137.66 74.86,135.52 R15.1@74.46,135.12
NetC19_2: C19.2 D12.2 D14.2 R24.2 U3.3 | length 22.8
  Top Layer w0.635: v1(69.85,29.845) 77.3,29.845 v1(77.47,30.015)
  Bottom Layer w0.381: U3.3@74.15,31.1 75.115,31.1 D14.2@76.2,30.015
  Bottom Layer w0.635: D12.2@67.945,31.074 68.069,30.95 C19.2@69.85,30.95 v1(69.85,29.845) ; D14.2@76.2,30.015 v1(77.47,30.015) 82.72,30.015 83.82,31.115 R24.2@83.82,32.625
NetC20_1: C20.1 Q6.2 R19.2 | length 72.5
  Signal Layer 1 w0.508: v1(7.62,60.706) 7.62,60.833 5.461,58.674 5.461,28.321 7.366,26.416 14.478,26.416 15.748,27.686 32.004,27.686 35.56,24.13 v1(35.56,22.479)
  Bottom Layer w0.508: v1(7.62,60.706) 7.62,62.192 R19.2@7.658,62.23 ; C20.1@33.655,21.425 35.48,21.425 35.48,22.399 v1(35.56,22.479)
NetC22_1: C22.1 D19.3 Q9.3 R27.1 R34.1 R36.2 U6.2 | length 17.7
  Bottom Layer w0.508: D19.3@26.67,24.7 27.624,24.7 27.94,24.384 R34.1@27.94,22.865 28.443,22.865 29.083,22.225 29.083,21.463 ; R36.2@27.94,19.69 28.453,19.69 29.083,20.32 29.083,21.463 ; Q9.3@34.925,25.97 32.785,25.97 R27.1@32.385,26.37 32.385,25.1 C22.1@31.915,24.63 32.065,24.48 U6.2@32.065,22.79 30.738,21.463 29.083,21.463
NetC22_2: C22.2 C26.2 R23.1 U5.2 U6.1 | length 72.4
  Signal Layer 1 w0.508: v1(5.842,60.833) 5.715,60.833 4.699,59.817 4.699,28.005 7.05,25.654 14.794,25.654 15.683,26.543 v1(31.115,26.543)
  Bottom Layer w0.508: v1(5.842,60.833) 5.762,60.833 5.05,61.545 5.05,63.032 5.08,63.062 5.08,63.157 R23.1@6.058,64.135 6.223,64.3 U5.2@6.223,66.065 ; U6.1@30.165,22.79 30.165,24.48 C22.2@30.315,24.63 30.315,25.9 C26.2@29.845,26.37 30.942,26.37 v1(31.115,26.543)
NetC23_1: C23.1 Q8.3 U4.8 | length 7.6
  Bottom Layer w0.457: 49.15,138.684 U4.8@49.917,137.917
  Bottom Layer w0.508: Q8.3@45.72,140.9 45.72,139.7 46.482,138.938 46.482,138.303 ; C23.1@46.429,137.539 46.482,137.593 46.482,138.303 ; 49.15,138.684 46.863,138.684 46.482,138.303
NetC24_1: C24.1 R18.1 R33.2 U4.6 | length 11.9
  Bottom Layer w0.457: U4.6@49.917,136.617 51.343,136.617
  Bottom Layer w0.508: C24.1@49.695,133.985 R33.2@51.905,133.985 ; 51.343,136.617 51.943,136.017 51.943,134.023 R33.2@51.905,133.985 ; R18.1@55.588,133.985 55.626,133.947 55.626,133.26 55.368,133.002 52.201,133.002 51.905,133.298 R33.2@51.905,133.985
NetC25_1: C25.1 R33.1 U4.3 | length 11.6
  Bottom Layer w0.457: 52.797,136.617 U4.3@54.117,136.617 55.28,136.617
  Bottom Layer w0.508: 52.797,136.617 52.705,136.525 52.705,135.509 53.505,134.709 R33.1@53.505,133.985 ; 55.28,136.617 56.388,135.509 59.69,135.509 C25.1@59.69,136.741
NetC26_1: C26.1 R27.2 | length 2.5
  Bottom Layer w0.508: C26.1@29.845,27.97 R27.2@32.385,27.97
NetC27_1: C27.1 Q7.3 R30.2 | length 3.6
  Bottom Layer w0.508: Q7.3@53.27,146.05 54.699,146.05 C27.1@55.08,146.431 R30.2@55.08,144.78
NetC28_1: C28.1 L2.2 R24.1 R28.2 | length 20.5
  Top Layer w1.27: 86.995,23.876 88.646,25.527 v1(90.043,25.527)
  Bottom Layer w1.27: R24.1@83.82,37.225 85.104,35.941 C28.1@86.995,35.941 89.281,35.941 90.043,35.179 v1(90.043,25.527)
  other v2: 80.264,12.954 80.264,14.732
NetC29_1: C29.1 U4.1 U5.4 | length 99.2
  Signal Layer 1 w0.508: v1(7.493,73.787) 7.493,82.296 6.604,83.185 6.604,89.154 18.034,100.584 18.034,109.093 29.591,120.65 29.591,129.54 39.878,139.827 41.18,139.827 42.173,140.82 46.505,140.82 47.498,139.827 50.038,139.827 50.165,139.7 v1(53.37,139.7)
  Bottom Layer w0.457: U4.1@54.117,137.917 54.117,138.953
  Bottom Layer w0.508: U5.4@7.493,72.365 v1(7.493,73.787) ; C29.1@52.235,139.7 v1(53.37,139.7) 54.117,138.953
NetC30_1: C30.1 R37.1 | length 2
  Bottom Layer w0.508: C30.1@21.844,25.4 22.06,25.184 R37.1@22.06,23.495
NetC30_2: C30.2 D19.1 D20.3 R40.1 | length 9.5
  Bottom Layer w0.508: D20.3@20.32,29.775 20.855,29.24 R40.1@23.495,29.24 24.1,29.24 24.765,28.575 24.765,27.305 ; C30.2@23.876,25.4 24.74,26.264 24.74,27.28 24.765,27.305 ; D19.1@25.72,27.1 25.515,27.305 24.765,27.305
NetC31_1: C31.1 Q9.1 R44.2 R49.2 | length 9.2
  Bottom Layer w0.508: R44.2@29.845,32.415 R49.2@31.75,32.415 32.22,32.885 33.02,32.885 ; C31.1@33.909,32.885 33.02,32.885 ; Q9.1@33.975,28.37 33.02,29.325 33.02,32.885
NetC33_2: C33.2 TP12.1 | length 6.5
  Bottom Layer w1.27: TP12.1@11.684,132.334 13.208,130.81 C33.2@17.6,130.81
NetC34_2: C34.2 C37.1 L3.1 L5.7 R55.2 | length 4.2
  Bottom Layer w1.27: L5.7@57.5,158.83 57.76,158.57 R55.2@61.595,158.57
NetC37_2: C37.2 C60.1 L5.9 L8.1 R60.1 | length 4.3
  Bottom Layer w1.27: L5.9@57.5,168.83 57.58,168.91 59.055,168.91 59.51,168.455 R60.1@61.595,168.455
NetC38_1: C38.1 D24.2 D26.1 L4.6
  other v2: 41.656,112.268 43.434,112.268 41.656,113.665 43.434,113.665
NetC38_2: C38.2 D26.4 R61.1 R63.1 R64.2
NetC39_1: C39.1 R62.1 R66.2 U9.6 | length 15.6
  Bottom Layer w0.508: U9.6@29.07,139.065 31.585,139.065 C39.1@31.75,138.9 R66.2@33.655,138.9 33.655,139.492 34.34,139.492 34.638,139.79 34.638,146.398 35.74,147.5 R62.1@36.83,147.5
NetC40_1: C40.1 C41.1 R65.1 | length 5.5
  Bottom Layer w0.508: C41.1@27.051,147.32 C40.1@27.051,144.78 27.521,144.31 R65.1@29.845,144.31
NetC42_1: C42.1 R65.2 U9.5 | length 4.6
  Bottom Layer w0.508: U9.5@29.07,140.335 29.845,141.11 R65.2@29.845,142.71 C42.1@31.75,142.71
NetC43_1: C43.1 D28.3 R64.1 U9.3 | length 10.9
  Bottom Layer w0.508: C43.1@19.685,137.96 19.685,138.43 20.32,139.065 20.955,139.065 ; R64.1@20.955,144.615 D28.3@20.955,142.805 20.955,139.065 ; U9.3@24.27,139.065 20.955,139.065
NetC44_1: C44.1 U9.2 | length 2.7
  Bottom Layer w0.508: C44.1@21.59,137.96 21.755,137.795 U9.2@24.27,137.795
NetC48_1: C48.1 C49.1 J4.1 L10.2 R74.2 TP23.1
NetC53_1: C53.1 C54.1 R75.1 R76.2 U11.2 | length 48.8
  Signal Layer 1 w0.381: v1(9.525,82.423) 9.53,82.418 12.319,82.418 12.319,89.535 19.685,96.901 v1(19.685,98.425)
  Bottom Layer w0.381: R76.2@8.725,80.772 8.725,81.623 v1(9.525,82.423) ; v1(19.685,98.425) 20.574,98.425 22.154,100.005 U11.2@23.3,100.005 24.44,100.005 24.638,100.203 24.638,101.854 23.241,103.251 23.241,105.156 23.495,105.41 C54.1@24.6,105.41
  Bottom Layer w0.508: C54.1@24.6,105.41 24.6,106.388 25.146,106.934 27.622,106.934 R75.1@29.171,105.385
  Bottom Layer w1.016: R76.2@8.725,80.772 8.725,79.667 10.557,77.835 C53.1@12.7,77.835
NetC55_1: C55.1 U11.8 | length 3.2
  Bottom Layer w0.457: U11.8@27.5,99.355 28.534,99.355 29.21,98.679 C55.1@30.442,98.679
NetC56_1: C56.1 U11.3 | length 2.7
  Bottom Layer w0.457: C56.1@20.701,100.8 20.846,100.655 U11.3@23.3,100.655
NetC57_1: C57.1 U11.1 U12.4 | length 39.9
  Signal Layer 1 w0.381: v1(19.304,94.996) 19.304,93.98 18.231,92.907 18.231,75.381 19.445,74.168 v1(22.225,74.168) v1@22.225,74.041
  Bottom Layer w0.381: v1(19.304,94.996) 19.177,94.996 19.177,95.885 22.647,99.355 U11.1@23.3,99.355 24.679,99.355 25.4,99.83 ; U12.4@22.225,72.365 v1(22.225,74.168) ; C57.1@24.6,103.759 24.6,103.162 25.781,101.981 25.781,101.219 25.4,100.83 25.4,99.84
NetC58_1: C58.1 R83.1 R85.1 R86.2 U13.1 | length 7.4
  Bottom Layer w0.508: R83.1@17.145,60.49 R86.2@19.05,60.49 19.897,60.49 20.481,59.906 R85.1@20.574,59.906 20.79,59.69 C58.1@20.79,58.42 20.64,58.27 U13.1@20.64,56.295
NetC58_2: C58.2 C59.2 R84.1 U13.2 | length 8.9
  Bottom Layer w0.508: R84.1@22.39,63.5 22.39,63.335 23.749,61.976 23.749,60.325 23.33,59.906 C59.2@22.479,59.906 22.479,58.509 C58.2@22.39,58.42 22.54,58.27 U13.2@22.54,56.295
NetC59_1: C59.1 R85.2 | length 1.9
  Bottom Layer w0.508: R85.2@20.574,61.506 C59.1@22.479,61.506
NetD1_2: D1.2 R2.1 | length 2.8
  Bottom Layer w0.508: R2.1@64.95,146.685 D1.2@67.723,146.685
NetD4_2: D4.2 Q2.2 T1.2
  other v2: 70.231,117.983 71.628,117.983 70.231,119.38 71.628,119.38
NetD6_1: D6.1 Q3.2 Q3.4
NetD10_1: D10.1 R15.2 U2.1 U2.2 U4.4 | length 23.4
  Signal Layer 1 w0.508: v1(54.61,135.255) 56.642,135.255 57.785,136.398 62.499,136.398 63.369,135.529 71.481,135.529 71.755,135.255 v1(72.009,135.509)
  Bottom Layer w0.457: U4.4@54.117,135.967 v1@54.61,135.474
  Bottom Layer w0.508: v1(54.61,135.255) v1@54.61,135.474 ; U2.2@69.35,135.529 U2.1@70.62,135.529 71.481,135.529 71.755,135.255 v1(72.009,135.509) ; R15.2@72.46,135.52 D10.1@72.46,136.71
NetD13_1: D13.1 R16.1 R17.1 | length 7
  Bottom Layer w0.762: R16.1@80.01,34.11 80.175,33.945 R17.1@80.175,31.75
  Bottom Layer w1.27: D13.1@76.295,36.195 78.38,34.11 R16.1@80.01,34.11
NetD13_2: D13.2 D17.1 | length 3
  Bottom Layer w1.524: D17.1@69.31,36.195 D13.2@72.295,36.195
NetD14_1: D14.1 R17.2 U3.2 | length 4.8
  Bottom Layer w0.381: U3.2@74.15,31.75 75.425,31.75 75.89,32.215 D14.1@76.2,32.215
  Bottom Layer w0.508: D14.1@76.2,32.215 76.665,31.75 R17.2@78.575,31.75
NetD15_1: D15.1 L2.1 Q5.2 Q5.4 | length 5.8
  Bottom Layer w1.27: Q5.4@73.025,21.23 Q5.2@73.025,27.03
  other v2: 71.755,18.415 73.66,18.415 75.565,18.415 81.915,18.415 76.835,20.32 81.915,20.32 76.835,22.86
NetD16_1: D16.1 Q6.1 R21.2 | length 4.6
  Bottom Layer w0.508: Q6.1@37.78,21.025 39.605,21.025 R21.2@39.835,21.255 ; D16.1@39.835,19.05 R21.2@39.835,21.255 ; R21.2@40.005,21.425 R21.2@39.835,21.255
NetD18_1: D18.1 R31.1 U7.2 | length 9.7
  Bottom Layer w0.254: R31.1@54.61,140.805 54.648,140.843 55.753,140.843 56.631,141.751 57.547,141.751 58.29,142.494 58.701,142.494 U7.2@58.989,142.782
  Bottom Layer w0.508: D18.1@51.985,143.51 52.451,143.51 53.34,142.621 53.34,141.388 53.885,140.843 54.572,140.843 R31.1@54.61,140.805
NetD18_2: D18.2 R35.1 | length 2.5
  Bottom Layer w0.635: R35.1@48.425,143.51 D18.2@50.885,143.51
NetD21_1: D21.1 R45.2 | length 6.6
  Top Layer w0.381: D21.1@10.38,33.02 10.38,33.748 10.706,34.074 13.268,34.074 13.687,33.655 v1(14.732,33.655)
  Bottom Layer w0.508: R45.2@13.5,33.655 v1(14.732,33.655)
NetD21_2: D21.2 Q13.3 Q14.1 | length 10.6
  Top Layer w0.508: D21.2@12.48,33.02 13.623,31.877 16.51,31.877 17.399,32.766 v1(17.399,33.02) 18.161,33.02 v1(19.431,34.29)
  Bottom Layer w0.508: Q14.1@17.399,31.881 v1(17.399,33.02) ; v1(19.431,34.29) 20.25,34.29 Q13.3@20.32,34.22
NetD22_1: D22.1 R46.2 | length 4.6
  Top Layer w0.508: v1(7.62,31.877) 9.107,30.57 D22.1@10.38,30.57
  Bottom Layer w0.508: v1(7.62,31.877) R46.2@8.89,31.585
NetD22_2: D22.2 Q14.3 | length 7.4
  Top Layer w0.508: D22.2@12.48,30.57 12.55,30.5 v1(14.76,30.5)
  Bottom Layer w0.381: 16.445,31.157 Q14.3@16.445,34.155
  Bottom Layer w0.508: v1(14.76,30.5) 15.788,30.5 16.445,31.157 ; Q14.3@16.445,34.155 Q14.3@16.51,34.22
NetD23_1: D23.1 R54.2 | length 6.8
  Top Layer w0.508: v1@9.017,29.591 v1(9.017,29.337) 9.017,29.303 D23.1@10.38,27.94
  Bottom Layer w0.508: v1(9.017,29.337) 9.017,30.019 10.541,31.543 10.541,31.75 11.303,31.75 ; R54.2@11.43,31.877 11.303,31.75 ; R54.2@11.9,31.75 11.303,31.75
NetD25_2: D25.2 L4.1 Q15.2
NetD26_2: D26.2 L3.2
NetD26_3: D26.3 RT1.1
NetD27_1: D27.1 Q16.1 R67.1 | length 4.2
  Bottom Layer w0.508: D27.1@8.57,27.375 8.96,27.375 9.525,27.94 10.41,27.94 Q16.1@10.48,27.87 10.48,29.695 R67.1@10.63,29.845
NetD27_3: D27.3 J3.2 | length 30.5
  Bottom Layer w0.508: D27.3@7.62,29.775 6.35,31.045 6.35,53.213 9.779,56.642 11.303,56.642 J3.2@11.43,56.515
NetD29_1: D29.1 Q17.1 R70.2 | length 4.8
  Bottom Layer w0.635: D29.1@16.721,96.534 16.721,97.376 16.421,97.676 R70.2@16.421,98.312 16.421,99.08 16.905,99.564 Q17.1@16.905,101
NetD30_2: D30.2 T2.7 | length 4.9
  Bottom Layer w2.032: T2.7@33.06,60.08 33.06,59.745 D30.2@36.29,56.515
NetD31_1: D31.1 R72.2 | length 3.1
  Bottom Layer w1.27: R72.2@39.116,89.535 39.751,89.535 40.481,90.265 D31.1@41.91,90.265
NetD32_1: D32.1 R72.1 | length 2.7
  Bottom Layer w1.016: D32.1@34.385,89.535 R72.1@37.084,89.535
NetD32_2: D32.2 Q18.4 T2.3
NetD33_2: D33.2 D34.1 T2.5 | length 16.7
  Signal Layer 1 w0.635: v1(21.844,79.375) 24.139,77.08 T2.5@28.56,77.08
  Bottom Layer w0.635: D34.1@14.662,81.595 15.49,82.423 19.163,82.423 D33.2@20.814,80.772 20.814,80.405 v1(21.844,79.375)
NetD34_3: D34.3 R76.1 | length 2
  Bottom Layer w0.635: R76.1@10.325,80.772 10.452,80.645 D34.3@12.262,80.645
NetF1_1: L5.4 RV1.2 XF2.1 XF2.2
NetF1_2: TP17.1 XF1.1 XF1.2
NetJ3_1: J3.1 R43.1 | length 39.7
  Bottom Layer w0.508: R43.1@6.82,25.4 6.35,25.4 5.461,26.289 5.461,57.046 8.43,60.015 J3.1@11.43,60.015
NetJ3_3: J3.3 S1.4 | length 16
  Signal Layer 1 w1.016: S1.4@8.89,38.1 8.89,50.475 J3.3@11.43,53.015
NetJ5_2: J5.2 Q10.3 R42.1 | length 13.1
  Bottom Layer w0.381: 18.384,31.273 18.384,35.275
  Bottom Layer w0.508: Q10.3@16.51,29.775 16.886,29.775 18.384,31.273 ; 18.384,35.275 19.685,36.576 20.32,35.941 21.874,35.941 R42.1@23.495,34.32
NetL5_2: L5.2 RV1.1 TP19.1
NetL8_2: L8.2 RT1.2
NetL11_1: L11.1 U10.3 | length 11.7
  Signal Layer 1 w0.635: v1(25.273,43.18) 28.194,43.18 31.369,40.005 v1(31.369,38.735)
  Bottom Layer w0.635: v1(25.273,43.18) 25.838,42.615 U10.3@26.355,42.615 ; L11.1@29.69,38.735 v1(31.369,38.735)
NetQ1_1: Q1.1 R7.2 R8.1 | length 8.5
  Bottom Layer w0.635: R7.2@76.835,125.565 76.855,125.585 80.213,125.585 Q1.1@80.213,125.727 80.264,125.676 80.264,123.19 80.899,122.555 R8.1@82.385,122.555
NetQ2_1: Q2.1 R10.2 R13.1 | length 7.5
  Bottom Layer w1.016: Q2.1@64.335,125.705 64.335,129.175 R10.2@64.135,129.375 67.615,129.375 R13.1@67.78,129.54
NetQ2_3: Q2.3 R13.2 R14.2 R18.2 | length 9.3
  Bottom Layer w0.508: R18.2@57.442,133.985 58.293,133.985 59.69,132.588 R14.2@59.69,129.95
  Bottom Layer w0.635: R13.2@69.38,129.54 69.415,129.505 Q2.3@69.415,125.705
  other v2: 58.293,131.572 59.817,131.572 61.468,131.572
NetQ3_1: Q3.1 Q4.3 R11.1 | length 9.9
  Bottom Layer w0.635: R11.1@75.73,144.145 77.203,144.145 77.4,143.948 ; Q4.3@77.4,141.605 77.4,143.948 ; Q3.1@82.155,146.41 79.693,143.948 77.4,143.948
NetQ5_1: Q5.1 U3.4 | length 4.6
  Bottom Layer w0.635: Q5.1@70.725,27.03 70.725,28.815 71.755,29.845 71.755,30.955 U3.4@71.9,31.1
NetQ7_1: Q7.1 R22.1 R31.2 | length 7.4
  Bottom Layer w0.508: Q7.1@50.87,145.1 52.639,145.1 54.737,143.002 54.61,142.875 R31.2@54.61,142.405
  Bottom Layer w0.635: R22.1@48.895,145.25 50.72,145.25 Q7.1@50.87,145.1
NetQ8_1: Q8.1 R35.2 R39.2 | length 7.3
  Bottom Layer w0.635: R35.2@46.825,143.51 46.825,143.04 47.945,141.92 Q8.1@48.19,141.92 48.849,141.92 49.327,142.398 51.748,142.398 52.07,142.076 52.07,141.516 R39.2@52.235,141.351
NetQ9_2: Q9.2 R48.1 | length 2
  Bottom Layer w0.508: R48.1@35.725,30.345 35.725,28.52 Q9.2@35.875,28.37
NetQ11_1: Q11.1 R41.2 R42.2 | length 4.5
  Bottom Layer w0.508: R42.2@23.495,32.72 25.705,32.72 R41.2@25.87,32.885 25.87,31.06 Q11.1@25.72,30.91
NetQ11_3: Q11.3 R44.1 | length 4.1
  Bottom Layer w0.508: Q11.3@26.67,28.51 27.54,28.51 R44.1@29.845,30.815
NetQ12_1: Q12.1 R50.1 R52.2 | length 5.8
  Bottom Layer w0.508: R50.1@14.77,90.17 14.77,91.995 Q12.1@14.92,92.145 14.92,93.279 15.786,94.145 R52.2@17.145,94.145
NetQ15_1: Q15.1 R57.1 R58.2 | length 6.8
  Bottom Layer w1.27: Q15.1@33.655,125.73 33.401,125.984 R57.1@33.401,130.175 34.036,129.54 R58.2@35.395,129.54
NetQ18_1: Q18.1 U11.4 | length 8.9
  Signal Layer 1 w0.508: v1(22.479,97.028) 22.733,97.282 v1(22.733,102.362)
  Bottom Layer w0.381: U11.4@23.3,101.305 23.3,101.795
  Bottom Layer w0.508: v1(22.479,97.028) 22.479,94.846 Q18.1@22.485,94.84 ; v1(22.733,102.362) 23.3,101.795
NetQ18_3: Q18.3 R79.2 R81.2 | length 5.7
  Bottom Layer w0.635: R79.2@27.47,97.155 27.47,95.265 Q18.3@27.045,94.84 28.805,94.84 R81.2@29.845,93.8
NetR4_1: R4.1 U1.1 | length 2
  Bottom Layer w0.508: R4.1@53.048,47.371 53.048,46.262 U1.1@53.66,45.65
NetR5_2: R5.2 R6.1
